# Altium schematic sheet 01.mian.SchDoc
size A4; Author: 刘时杰; CompanyName: 广州致远电子有限公司; DocumentNumber: 1; SheetNumber: 1; SheetTotal: 8; PageSetup: Record=PageOptions|CenterHorizontal=True|CenterVertical=True|PrintScale=1.00|XCorrection=1.00|YCorrection=1.00|PrintKind=0|BorderSize=5000000|LeftOffset=0|BottomOffset=0|Orientation=2|PaperLength=1000|PaperWidth=1000|Scale=100|PaperSource=7|PrintQuality=600|MediaType=1|DitherType=10|PaperKind=A4|PrintScaleMode=1; DesignDate: 20180913; CheckDate: 20180913; SheetName: mian; SheetVersion: V1.00; SheetDescription: AML166 评估板; ProductName: AML166-Core; ProductModel: AML166
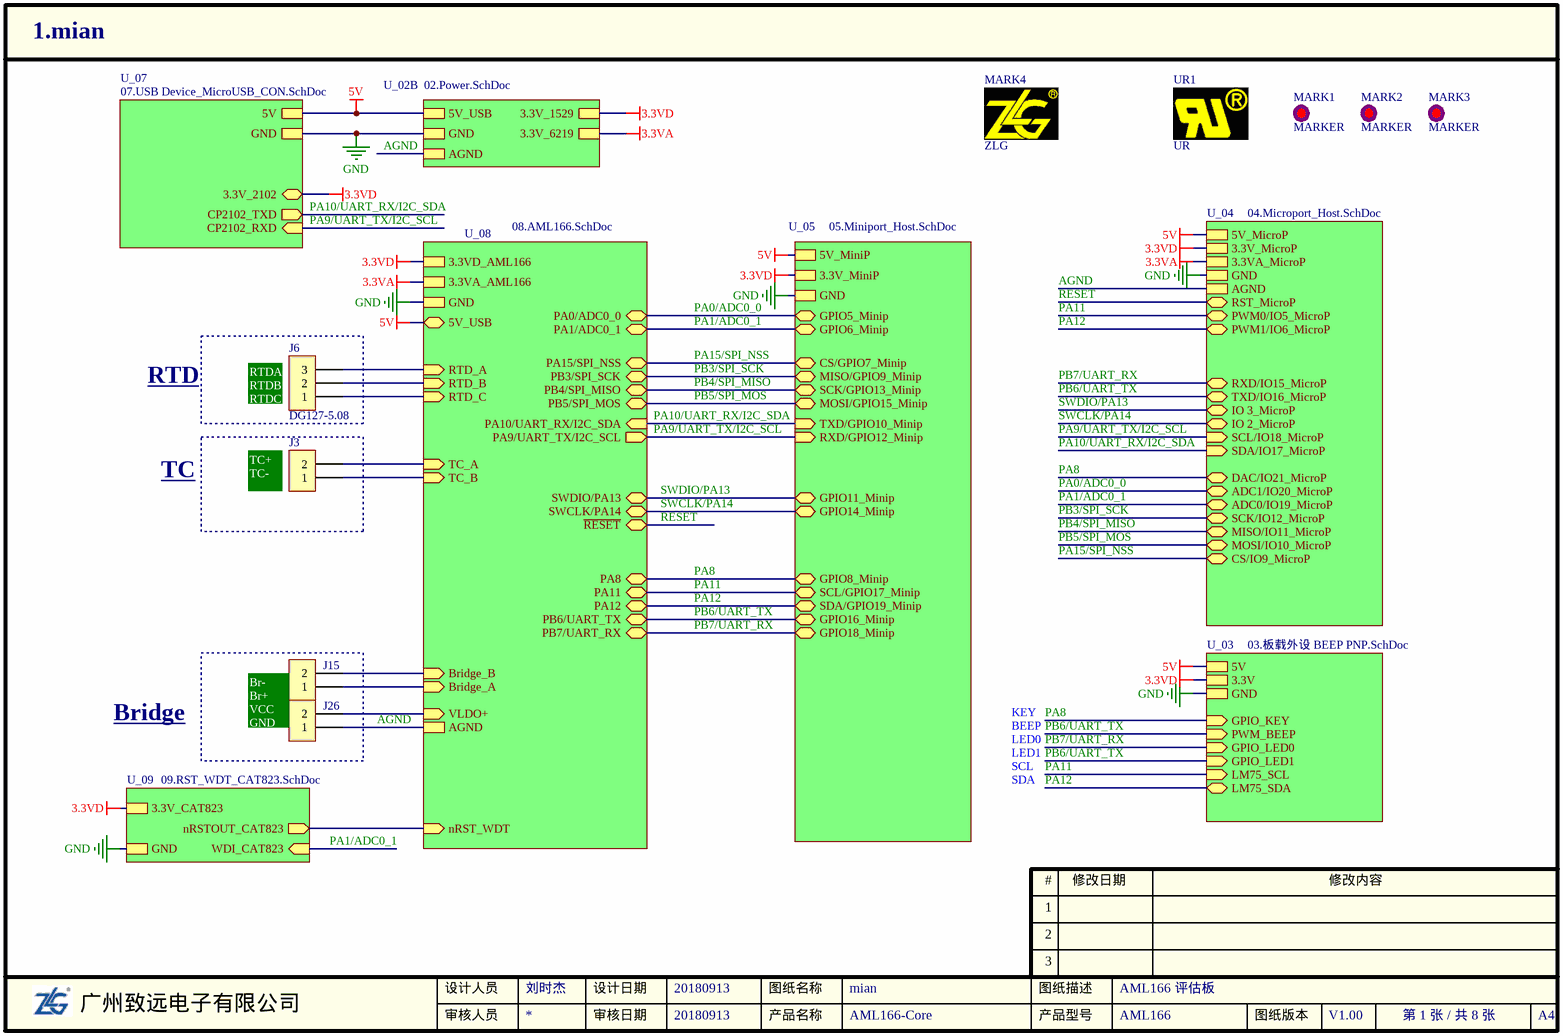
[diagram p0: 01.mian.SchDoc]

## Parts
J3  (no value)  [CON508P810W130D15S-2DIP]
J6  DG127-5.08  [CON508P1524L810W110D15S-3DIP]
J15  (no value)  [CON508P810W130D15S-2DIP]
J26  (no value)  [CON508P810W130D15S-2DIP]
MARK1  MARKER  [MARKER-C-1.0M]  (no BOM)
MARK2  MARKER  [MARKER-C-1.0M]  (no BOM)
MARK3  MARKER  [MARKER-C-1.0M]  (no BOM)
MARK4  ZLG  [ZLG0.7]  (no BOM)
UR1  UR  [ZY_UR-3X2]  (no BOM)

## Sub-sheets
U_02B = 02.Power.SchDoc: GND, 5V_USB, 3.3V_1529, 3.3V_6219, AGND
U_03 = 03.板载外设 BEEP PNP.SchDoc: GND, 3.3V, PWM_BEEP (in), GPIO_LED0 (in), GPIO_LED1 (in), 5V, LM75_SCL (in), LM75_SDA (bidir), GPIO_KEY (in)
U_04 = 04.Microport_Host.SchDoc: GND, 3.3V_MicroP, AGND, 5V_MicroP, 3.3VA_MicroP, RXD/IO15_MicroP (bidir), TXD/IO16_MicroP (bidir), MOSI/IO10_MicroP (bidir), SCK/IO12_MicroP (bidir), MISO/IO11_MicroP (bidir), IO 3_MicroP (bidir), IO 2_MicroP (bidir), PWM1/IO6_MicroP (bidir), PWM0/IO5_MicroP (bidir), SDA/IO17_MicroP (in), SCL/IO18_MicroP (in), ADC1/IO20_MicroP (bidir), ADC0/IO19_MicroP (bidir), DAC/IO21_MicroP (bidir), RST_MicroP (bidir), CS/IO9_MicroP (bidir)
U_05 = 05.Miniport_Host.SchDoc: GND, 3.3V_MiniP, 5V_MiniP, MISO/GPIO9_Minip (bidir), GPIO5_Minip (bidir), MOSI/GPIO15_Minip (bidir), SCK/GPIO13_Minip (bidir), GPIO11_Minip (bidir), CS/GPIO7_Minip (bidir), GPIO14_Minip (bidir), GPIO6_Minip (bidir), RXD/GPIO12_Minip (in), TXD/GPIO10_Minip (in), GPIO8_Minip (bidir), GPIO16_Minip (bidir), SDA/GPIO19_Minip (bidir), SCL/GPIO17_Minip (bidir), GPIO18_Minip (bidir)
U_07 = 07.USB Device_MicroUSB_CON.SchDoc: 5V, GND, CP2102_TXD (out), CP2102_RXD (in), 3.3V_2102
U_08 = 08.AML166.SchDoc: nRST_WDT (in), 3.3VD_AML166, PA10/UART_RX/I2C_SDA (in), PA15/SPI_NSS (bidir), PA0/ADC0_0 (bidir), PA1/ADC0_1 (bidir), PA9/UART_TX/I2C_SCL (out), PB3/SPI_SCK (bidir), PB5/SPI_MOS (bidir), PA11 (bidir), PA12 (bidir), PB7/UART_RX (bidir), PB4/SPI_MISO (bidir), PA8 (bidir), PB6/UART_TX (bidir), GND, RTD_A (in), RTD_B (in), RTD_C (in), TC_A (in), TC_B (in), AGND, SWDIO/PA13 (bidir), SWCLK/PA14 (bidir), ~{RESET} (bidir), 3.3VA_AML166, Bridge_A (in), Bridge_B (in), VLDO+ (in), 5V_USB
U_09 = 09.RST_WDT_CAT823.SchDoc: GND, 3.3V_CAT823, WDI_CAT823 (in), nRSTOUT_CAT823 (out)

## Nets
3.3VA: sheet U_08/3.3VA_AML166, sheet U_04/3.3VA_MicroP, sheet U_02B/3.3V_6219
3.3VD: sheet U_08/3.3VD_AML166, sheet U_05/3.3V_MiniP, sheet U_04/3.3V_MicroP, sheet U_03/3.3V, sheet U_02B/3.3V_1529, sheet U_09/3.3V_CAT823, sheet U_07/3.3V_2102
5V: sheet U_08/5V_USB, sheet U_05/5V_MiniP, sheet U_04/5V_MicroP, sheet U_03/5V, sheet U_02B/5V_USB, sheet U_07/5V
GND: sheet U_08/GND, sheet U_05/GND, sheet U_04/GND, sheet U_03/GND, sheet U_02B/GND, sheet U_09/GND, sheet U_07/GND
AGND: J26.1 ; sheet U_08/AGND, sheet U_04/AGND, sheet U_02B/AGND
PA0/ADC0_0: sheet U_08/PA0/ADC0_0, sheet U_05/GPIO5_Minip, sheet U_04/ADC1/IO20_MicroP
PA1/ADC0_1: sheet U_08/PA1/ADC0_1, sheet U_05/GPIO6_Minip, sheet U_04/ADC0/IO19_MicroP, sheet U_09/WDI_CAT823
PA8: sheet U_08/PA8, sheet U_05/GPIO8_Minip, sheet U_04/DAC/IO21_MicroP, sheet U_03/GPIO_KEY
PA9/UART_TX/I2C_SCL: sheet U_08/PA9/UART_TX/I2C_SCL, sheet U_05/RXD/GPIO12_Minip, sheet U_04/SCL/IO18_MicroP, sheet U_07/CP2102_RXD
PA10/UART_RX/I2C_SDA: sheet U_08/PA10/UART_RX/I2C_SDA, sheet U_05/TXD/GPIO10_Minip, sheet U_04/SDA/IO17_MicroP, sheet U_07/CP2102_TXD
PA11: sheet U_08/PA11, sheet U_05/SCL/GPIO17_Minip, sheet U_04/PWM0/IO5_MicroP, sheet U_03/LM75_SCL
PA12: sheet U_08/PA12, sheet U_05/SDA/GPIO19_Minip, sheet U_04/PWM1/IO6_MicroP, sheet U_03/LM75_SDA
PA15/SPI_NSS: sheet U_08/PA15/SPI_NSS, sheet U_05/CS/GPIO7_Minip, sheet U_04/CS/IO9_MicroP
PB3/SPI_SCK: sheet U_08/PB3/SPI_SCK, sheet U_05/MISO/GPIO9_Minip, sheet U_04/SCK/IO12_MicroP
PB4/SPI_MISO: sheet U_08/PB4/SPI_MISO, sheet U_05/SCK/GPIO13_Minip, sheet U_04/MISO/IO11_MicroP
PB5/SPI_MOS: sheet U_08/PB5/SPI_MOS, sheet U_05/MOSI/GPIO15_Minip, sheet U_04/MOSI/IO10_MicroP
PB6/UART_TX: sheet U_08/PB6/UART_TX, sheet U_05/GPIO16_Minip, sheet U_04/TXD/IO16_MicroP, sheet U_03/PWM_BEEP, sheet U_03/GPIO_LED1
PB7/UART_RX: sheet U_08/PB7/UART_RX, sheet U_05/GPIO18_Minip, sheet U_04/RXD/IO15_MicroP, sheet U_03/GPIO_LED0
~{RESET}: sheet U_08/~{RESET}, sheet U_04/RST_MicroP
SWCLK/PA14: sheet U_08/SWCLK/PA14, sheet U_05/GPIO14_Minip, sheet U_04/IO 2_MicroP
SWDIO/PA13: sheet U_08/SWDIO/PA13, sheet U_05/GPIO11_Minip, sheet U_04/IO 3_MicroP
NetJ3_1: J3.1 ; sheet U_08/TC_B
NetJ3_2: J3.2 ; sheet U_08/TC_A
NetJ6_1: J6.1 ; sheet U_08/RTD_C
NetJ6_2: J6.2 ; sheet U_08/RTD_B
NetJ6_3: J6.3 ; sheet U_08/RTD_A
NetJ15_1: J15.1 ; sheet U_08/Bridge_A
NetJ15_2: J15.2 ; sheet U_08/Bridge_B
NetJ26_2: J26.2 ; sheet U_08/VLDO+
(unnamed): sheet U_08/nRST_WDT, sheet U_09/nRSTOUT_CAT823

Not connected (* = marked no-connect by the designer): MARK1 0; MARK2 0; MARK3 0

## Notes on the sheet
- RTD
- (near J6) RTDA
  RTDB
  RTDC
- TC
- (near J3) TC+
  TC-
- KEY
- Bridge
- Br-
  Br+
  VCC
  GND
- BEEP
- LED0
- LED1
- SCL
- SDA

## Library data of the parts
J3 J15 J26 = 1.10.06.0070: DG127-5.08-02P-14-00AH,180°,绿色,DEGSON,RoHS; 名称: 端子; 贴片和直插: THT; PCB备注: xhm-lq-wyy-150126; 器件优选方案: 正常状态，可以选用
J6 = 19.04.00251: DG127-5.08-03P-14-00AH,180°,绿色,THT; 名称: 端子; PCB备注: 180925 yyf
